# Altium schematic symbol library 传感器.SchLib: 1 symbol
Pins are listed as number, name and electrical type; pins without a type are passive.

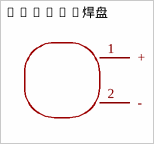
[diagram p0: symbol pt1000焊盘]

## pt1000焊盘
designator U??  (value not drawn)
AddInBom: yes
footprint PT1000焊盘
pins: 1 +, 2 -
